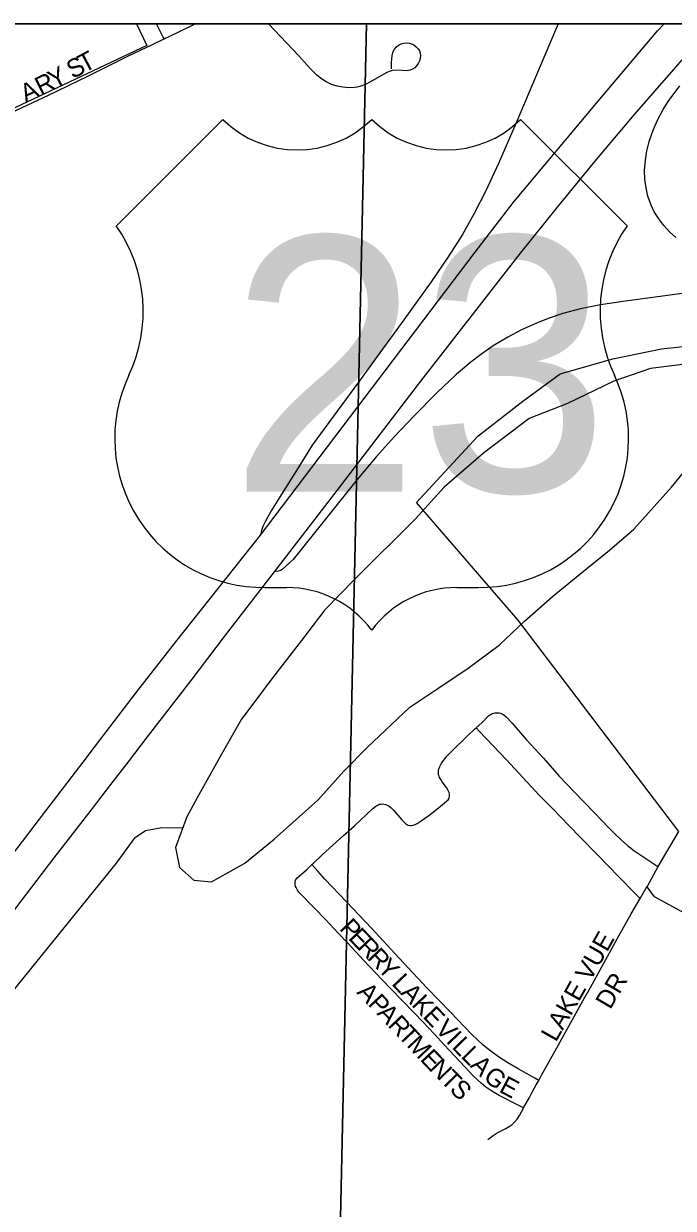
# Model space of a CAD drawing. Extents: x -5.6 to 34, y 0 to 22.
# Drawn here: x 7.127 to 7.835, y 19.608 to 20.9 of the extents above; entities that cross this region are included whole.
import ezdxf

# ---------------------------------------------------------------- set-up
doc = ezdxf.new("R2010")
doc.units = 0
for name, color, linetype in [('GM_X_City_Street', 7, 'Continuous'), ('GM_X_City_Street_Text', 7, 'Continuous'), ('GM_X_Corporation', 7, 'Continuous'), ('GM_X_Interchange_Ramps', 7, 'Continuous'), ('GM_X_Interstate_Route', 7, 'Continuous'), ('GM_X_Minor_Lake', 7, 'Continuous'), ('GM_X_Minor_River', 7, 'Continuous'), ('GM_X_Section', 7, 'Continuous'), ('GM_X_Township', 7, 'Continuous'), ('GM_X_US_Location', 7, 'Continuous'), ('GM_X_US_Route', 7, 'Continuous'), ('GM_X_US_Shield', 7, 'Continuous'), ('SH_Data', 7, 'Continuous')]:
    doc.layers.add(name, color=color, linetype=linetype)

msp = doc.modelspace()

# ---------------------------------------------------------------- linework, layer by layer
at = {"layer": 'GM_X_City_Street'}
for points in [[(7.2799, 20.8835), (7.279, 20.8853), (7.2717, 20.9)], [(7.2799, 20.8835), (7.2944, 20.8903), (7.3108, 20.8985), (7.3137, 20.9)], [(7.5277, 20.8508), (7.5278, 20.8577), (7.5286, 20.8651), (7.5291, 20.8684), (7.5307, 20.8718), (7.5332, 20.8749), (7.5356, 20.8766), (7.5383, 20.8779), (7.5412, 20.8787), (7.5441, 20.8791), (7.5469, 20.8789), (7.5495, 20.878), (7.5522, 20.8768), (7.5546, 20.8748), (7.5567, 20.8727), (7.5583, 20.8704), (7.5592, 20.8677), (7.5596, 20.8649), (7.5592, 20.8622), (7.5583, 20.8594), (7.5569, 20.8567), (7.5551, 20.8542), (7.5532, 20.852), (7.5508, 20.8504), (7.5482, 20.8493), (7.5447, 20.8486), (7.5391, 20.849), (7.5323, 20.8493), (7.5288, 20.8488), (7.5253, 20.8478), (7.5221, 20.8463), (7.505, 20.8365), (7.4993, 20.8337), (7.4933, 20.8315), (7.4903, 20.8308), (7.4873, 20.8304), (7.4809, 20.8301), (7.4746, 20.8306), (7.4684, 20.8318), (7.4624, 20.8338), (7.4566, 20.8365), (7.4513, 20.8398), (7.4464, 20.8439), (7.4395, 20.8507), (7.4263, 20.8653), (7.3935, 20.9)], [(6.9188, 20.7095), (6.9607, 20.7297), (6.988, 20.7427), (7.0306, 20.763), (7.0731, 20.7839), (7.1134, 20.8032), (7.1538, 20.8221), (7.1975, 20.8433), (7.241, 20.8649), (7.2671, 20.8774), (7.2799, 20.8835)], [(7.62, 20.132), (7.6262, 20.1374), (7.6337, 20.1449), (7.6348, 20.1458), (7.6361, 20.1466), (7.6375, 20.1474), (7.639, 20.1479), (7.6405, 20.1482), (7.642, 20.1484), (7.6435, 20.1484), (7.6451, 20.1482), (7.6466, 20.1478), (7.648, 20.1473), (7.6494, 20.1466), (7.6507, 20.1457), (7.6528, 20.1438), (7.6592, 20.137), (7.6748, 20.1193), (7.6934, 20.0989), (7.7107, 20.0792), (7.7269, 20.0621), (7.7488, 20.0394), (7.757, 20.031), (7.7644, 20.0233), (7.7712, 20.0164), (7.7781, 20.0098), (7.785, 20.0036), (7.7922, 19.9982), (7.7996, 19.993), (7.8173, 19.9814), (7.8186, 19.9805)], [(7.4411, 19.9827), (7.4427, 19.9842), (7.4522, 19.9933), (7.4755, 20.0145), (7.4873, 20.0249), (7.5075, 20.0439), (7.5108, 20.0465), (7.512, 20.0473), (7.5133, 20.0479), (7.5148, 20.0485), (7.5163, 20.0488), (7.518, 20.0489), (7.5196, 20.0488), (7.5211, 20.0484), (7.5225, 20.0479), (7.5251, 20.0464), (7.5273, 20.0447), (7.5303, 20.0418), (7.5347, 20.0367), (7.5389, 20.0317), (7.5415, 20.0289), (7.5433, 20.0273), (7.5452, 20.0262), (7.5461, 20.0258), (7.5482, 20.0254), (7.5492, 20.0254), (7.5515, 20.0257), (7.5536, 20.0265), (7.5558, 20.0275), (7.5589, 20.0296), (7.5686, 20.0364), (7.5768, 20.0429), (7.5878, 20.0519), (7.5895, 20.0535), (7.5906, 20.0552), (7.5912, 20.0572), (7.5912, 20.0593), (7.5907, 20.0614), (7.5897, 20.0635), (7.5878, 20.0667), (7.583, 20.073), (7.5815, 20.0754), (7.5801, 20.0779), (7.5796, 20.0793), (7.5792, 20.0808), (7.579, 20.0823), (7.579, 20.0838), (7.5791, 20.0853), (7.5795, 20.0868), (7.5804, 20.0896), (7.5825, 20.0933), (7.5848, 20.0967), (7.5883, 20.1009), (7.5938, 20.1067), (7.6106, 20.1233), (7.6184, 20.1305), (7.62, 20.132)], [(7.7988, 19.9456), (7.7934, 19.9512), (7.7757, 19.9694), (7.7644, 19.9809), (7.752, 19.9937), (7.7334, 20.0127), (7.7215, 20.0249), (7.7032, 20.0438), (7.6888, 20.0585), (7.6531, 20.0971), (7.6234, 20.1284), (7.62, 20.132)], [(7.6718, 19.7175), (7.6668, 19.72), (7.6452, 19.7308), (7.6371, 19.7355), (7.6327, 19.7384), (7.6305, 19.74), (7.6254, 19.7443), (7.6167, 19.7524), (7.6081, 19.7617), (7.5965, 19.7743), (7.5853, 19.7862), (7.5746, 19.7978), (7.5538, 19.8197), (7.5382, 19.8356), (7.5173, 19.8574), (7.4974, 19.8784), (7.4804, 19.8965), (7.4696, 19.9081), (7.4561, 19.9224), (7.4435, 19.9357), (7.4269, 19.9527), (7.4252, 19.955), (7.4238, 19.9576), (7.4232, 19.959), (7.4228, 19.9605), (7.4226, 19.9621), (7.4227, 19.9639), (7.4233, 19.9656), (7.4241, 19.9671), (7.4251, 19.9683), (7.4272, 19.9702), (7.4351, 19.977), (7.4411, 19.9827)], [(7.6883, 19.7474), (7.6841, 19.7497), (7.666, 19.7599), (7.6547, 19.7666), (7.6446, 19.7729), (7.6374, 19.778), (7.6313, 19.7829), (7.6274, 19.7863), (7.6216, 19.7916), (7.6151, 19.7979), (7.5922, 19.8216), (7.5667, 19.8481), (7.5362, 19.8807), (7.5059, 19.9135), (7.4786, 19.942), (7.4552, 19.9669), (7.4474, 19.9757), (7.4411, 19.9827)], [(7.7988, 19.9456), (7.8067, 19.9591)], [(7.7363, 19.8343), (7.7449, 19.8488), (7.7739, 19.9017), (7.7891, 19.9291), (7.7988, 19.9456)], [(7.6883, 19.7474), (7.6914, 19.7531), (7.7082, 19.783), (7.7363, 19.8343)], [(7.6718, 19.7175), (7.6782, 19.7288), (7.6812, 19.7346), (7.6837, 19.7392), (7.6857, 19.7426), (7.6883, 19.7474)], [(7.6329, 19.6827), (7.6356, 19.6852), (7.6386, 19.6874), (7.643, 19.69), (7.6524, 19.6948), (7.656, 19.6969), (7.6595, 19.6994), (7.6621, 19.7018), (7.6649, 19.7052), (7.6675, 19.7092), (7.6716, 19.7172), (7.6718, 19.7175)]]:
    msp.add_lwpolyline(points, dxfattribs=at)
at = {"layer": 'GM_X_Corporation'}
for points in [[(8.2067, 20.9), (4.0671, 20.9)], [(7.8921, 19.9053), (7.8147, 19.9475), (7.8065, 19.9586), (7.8186, 19.9805), (7.8412, 20.0189), (7.6656, 20.2498), (7.5552, 20.3778), (7.622, 20.45), (7.671, 20.4882), (7.7119, 20.5182), (7.7691, 20.5345), (7.8222, 20.5454), (7.859, 20.5495)]]:
    msp.add_lwpolyline(points, dxfattribs=at)
at = {"layer": 'GM_X_Interchange_Ramps'}
msp.add_lwpolyline([(7.8378, 20.6668), (7.8309, 20.673), (7.8247, 20.6798), (7.8192, 20.6871), (7.8144, 20.6949), (7.811, 20.702), (7.8074, 20.7119), (7.8054, 20.7209), (7.8041, 20.73), (7.8038, 20.7404), (7.8046, 20.7509), (7.8063, 20.7613), (7.8092, 20.7727), (7.8131, 20.7839), (7.8179, 20.7948), (7.8241, 20.8063), (7.8296, 20.8152), (7.8422, 20.8321)], dxfattribs=at)
at = {"layer": 'GM_X_Interstate_Route'}
for points in [[(7.3849, 20.342), (7.619, 20.6509), (7.6612, 20.7058), (7.7533, 20.8156), (7.8179, 20.8921), (7.8253, 20.9)], [(7.4684, 20.3909), (7.5571, 20.5067), (7.5917, 20.5513), (7.6684, 20.6497), (7.7087, 20.6999), (7.7512, 20.7517), (7.7928, 20.8009), (7.8377, 20.8524), (7.8448, 20.8604)], [(7.4003, 20.3021), (7.4684, 20.3909)], [(6.4434, 19.1203), (6.5045, 19.1998), (6.6774, 19.4249), (6.728, 19.4903), (6.7458, 19.5147), (6.7571, 19.5292), (6.7812, 19.5604), (6.8077, 19.5946), (6.8489, 19.6491), (6.8692, 19.6749), (6.8764, 19.6843), (6.9676, 19.803), (6.9901, 19.832), (7.0116, 19.8603), (7.0636, 19.928), (7.1256, 20.0079), (7.151, 20.0413), (7.1916, 20.0946), (7.2051, 20.1124), (7.2499, 20.1707), (7.2925, 20.2258), (7.3849, 20.342)], [(6.5864, 19.2428), (6.597, 19.2566), (6.6321, 19.3025), (6.6423, 19.3162), (6.7111, 19.4057), (6.7472, 19.4525), (6.7679, 19.4797), (6.8249, 19.5535), (6.8521, 19.5889), (6.9266, 19.6857), (6.9627, 19.7324), (6.9874, 19.7648), (7.0098, 19.794), (7.0433, 19.8378), (7.0866, 19.894), (7.1599, 19.99), (7.2017, 20.0441), (7.2216, 20.0702), (7.2411, 20.0949), (7.2619, 20.122), (7.3092, 20.1834), (7.3458, 20.2314), (7.4003, 20.3021)]]:
    msp.add_lwpolyline(points, dxfattribs=at)
at = {"layer": 'GM_X_Minor_Lake'}
msp.add_line((7.7332, 20.2995), (7.7654, 20.3256), dxfattribs=at)
for points in [[(7.8566, 20.5297), (7.8103, 20.5238), (7.7702, 20.5099), (7.7196, 20.4857), (7.6779, 20.4694), (7.628, 20.4315), (7.5852, 20.3944), (7.5536, 20.3595), (7.4882, 20.2946), (7.455, 20.2605), (7.4298, 20.2272), (7.4006, 20.1899), (7.3641, 20.1414), (7.3421, 20.1024), (7.3159, 20.0555), (7.3045, 20.0348), (7.2921, 20.0013), (7.2966, 19.9796), (7.3124, 19.9657), (7.3315, 19.9639), (7.3677, 19.9843), (7.3999, 20.0103), (7.4475, 20.053), (7.4759, 20.0847), (7.5017, 20.1109), (7.5478, 20.1544), (7.5784, 20.1748), (7.6114, 20.1969), (7.6452, 20.2221), (7.6727, 20.2482), (7.7033, 20.2751), (7.7332, 20.2995)], [(7.7654, 20.3256), (7.792, 20.3485), (7.8333, 20.3945), (7.8544, 20.4207)]]:
    msp.add_lwpolyline(points, dxfattribs=at)
at = {"layer": 'GM_X_Minor_River'}
msp.add_lwpolyline([(8.5297, 15.0523), (8.2755, 15.5636), (7.9273, 16.2717), (7.6894, 16.7524), (7.3893, 17.3541), (7.1716, 17.7937), (6.9143, 18.3107), (6.6663, 18.81), (6.5263, 19.0874), (6.6472, 19.2446), (6.7802, 19.4137), (6.9563, 19.6407), (7.1015, 19.8281), (7.228, 19.9844), (7.2483, 20.0122), (7.2596, 20.0201), (7.2772, 20.0231), (7.3001, 20.0228)], dxfattribs=at)
at = {"layer": 'GM_X_Section'}
for points in [[(7.5006, 20.9), (7.2498, 20.9), (7.2609, 20.8761), (5.343, 19.9706), (5.3166, 18.9352), (7.4578, 18.9294)], [(8.9, 18.906), (8.9, 20.9), (7.5006, 20.9), (7.4578, 18.9294)]]:
    msp.add_lwpolyline(points, close=True, dxfattribs=at)
at = {"layer": 'GM_X_Township'}
msp.add_lwpolyline([(3.0636, 14.1), (8.9, 14.1), (8.9, 20.9), (2.1, 20.9), (2.1, 16.9108), (2.7242, 16.8707), (3.1388, 16.8616), (3.0745, 14.7121)], close=True, dxfattribs=at)
at = {"layer": 'GM_X_US_Route'}
for points in [[(7.7097, 20.9), (7.6951, 20.8657), (7.6638, 20.792), (7.6443, 20.7474), (7.6306, 20.7175), (7.6181, 20.6929), (7.6051, 20.6701), (7.5904, 20.6468), (7.5712, 20.6185), (7.5413, 20.5769), (7.4919, 20.5089), (7.4414, 20.4403), (7.426, 20.4156), (7.4055, 20.3832), (7.3965, 20.3685), (7.3903, 20.3574), (7.3874, 20.3515), (7.386, 20.3472), (7.3849, 20.342)], [(7.8611, 20.608), (7.783, 20.5975), (7.7557, 20.5932), (7.7338, 20.5888), (7.7148, 20.5838), (7.6986, 20.5784), (7.6852, 20.5731), (7.6696, 20.566), (7.6546, 20.558), (7.6388, 20.5485), (7.6248, 20.5387), (7.6144, 20.5308), (7.5984, 20.5172), (7.5774, 20.4973), (7.5524, 20.4722), (7.5307, 20.4493), (7.5114, 20.4278), (7.4903, 20.4027), (7.4204, 20.3156), (7.413, 20.3085), (7.4087, 20.3048), (7.4068, 20.3037), (7.4042, 20.3027), (7.4003, 20.3021)]]:
    msp.add_lwpolyline(points, dxfattribs=at)
at = {"layer": 'GM_X_US_Shield'}
for p, q in [((7.3438, 20.7955), (7.2278, 20.6794)), ((7.7847, 20.6794), (7.6686, 20.7955)), ((7.3902, 20.285), (7.4134, 20.285)), ((7.599, 20.285), (7.6222, 20.285))]:
    msp.add_line(p, q, dxfattribs=at)
for centre, radius, start, end in [((7.425, 20.8783), 0.116, 225.573, 314.427), ((7.5874, 20.8783), 0.116, 225.573, 314.427), ((7.0947, 20.5863), 0.1624, 334.5471, 35.0009), ((7.9177, 20.5863), 0.1624, 144.9991, 205.4529), ((7.3884, 20.4474), 0.1624, 154.8319, 270.6383), ((7.624, 20.4474), 0.1624, 269.3617, 25.1681), ((7.4134, 20.169), 0.116, 36.8699, 90), ((7.599, 20.169), 0.116, 90, 143.1301)]:
    msp.add_arc(centre, radius, start, end, dxfattribs=at)
at = {"layer": 'SH_Data'}
msp.add_line((2.1, 20.9), (8.9, 20.9), dxfattribs=at)

# ---------------------------------------------------------------- texts
at = {"layer": 'GM_X_City_Street_Text'}
for s, rotation, p in [('T', 27.8964, (7.1926, 20.846)), ('S', 27.8973, (7.1801, 20.8394)), ('R', 26.5711, (7.1453, 20.8214)), ('Y', 27.8445, (7.1599, 20.8287)), ('A', 25.3513, (7.1289, 20.8136)), ('P', 313.4738, (7.4702, 19.9124)), ('E', 313.4821, (7.4799, 19.9021)), ('R', 313.4767, (7.4896, 19.8919)), ('LAKE VUE', 60.4605, (7.7071, 19.7883)), ('R', 313.4767, (7.5005, 19.8804)), ('Y', 313.4864, (7.5114, 19.8689)), ('L', 313.4738, (7.5271, 19.8523)), ('DR', 59.545, (7.7663, 19.8238)), ('A', 313.269, (7.4892, 19.8429)), ('A', 313.4705, (7.5368, 19.8421)), ('P', 313.2608, (7.5013, 19.8301)), ('K', 313.4864, (7.5489, 19.8293)), ('A', 313.2635, (7.511, 19.8199)), ('E', 313.4821, (7.561, 19.8166)), ('R', 313.2653, (7.523, 19.807)), ('V', 313.4705, (7.5744, 19.8025)), ('T', 313.2608, (7.5339, 19.7955)), ('M', 313.3312, (7.5435, 19.7852)), ('I', 313.4874, (7.5865, 19.7897)), ('L', 314.1056, (7.5927, 19.7832)), ('L', 314.87, (7.6027, 19.7729)), ('E', 313.6072, (7.5581, 19.7698)), ('N', 314.0754, (7.5679, 19.7595)), ('A', 315.2538, (7.6127, 19.7628)), ('T', 314.6922, (7.5803, 19.7467)), ('G', 320.6234, (7.6268, 19.749)), ('S', 314.9229, (7.5903, 19.7366)), ('E', 332.0883, (7.644, 19.7354))]:
    msp.add_text(s, height=0.02, rotation=rotation, dxfattribs=at).set_placement(p)
at = {"layer": 'GM_X_US_Location'}
for s in ['0', '/']:
    msp.add_text(s, height=0.0004, dxfattribs=at).set_placement((7.5061, 20.5264))
msp.add_text('23', height=0.0004, rotation=0, dxfattribs=at).set_placement((7.4235, 20.4436))
at = {"layer": 'GM_X_US_Shield'}
msp.add_text('23', height=0.27844, dxfattribs=at).set_placement((7.3512, 20.3894))

doc.saveas('drawing.dxf')
